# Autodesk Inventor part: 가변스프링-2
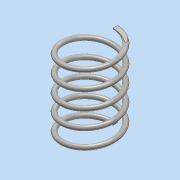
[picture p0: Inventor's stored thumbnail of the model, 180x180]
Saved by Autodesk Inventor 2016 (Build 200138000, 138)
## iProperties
Created: 2015-11
Part Number: 가변스프링-2
Material: 스테인레스 스틸
Document SubType Name: Modeling
Designer: Administrator
Density: 8 g/cm^3
Appearance: 반연마
Mass: 8.59389 g
Surface Area: 21.7235 cm^2
Volume: 1.07424 cm^3
Author: Administrator
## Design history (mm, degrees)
sketch "스케치2"
  geometry: L1 (0, 0)-(11, 0); L2 (11, 0)-(11, 36.561); L3 (11, 36.561)-(0, 36.561); L4 (0, 36.561)-(0, 0); C1 r 1 at (11, 0)
  constraints: 8 end point, 2 parallel, 1 centre point, 1 coincident, 1 horizontal, 1 perpendicular
  dimensions: "d0" = 2 diameter of C1; "d1" = 22 diameter of L2 L4; "d2" = 36.5612 distance between parallel lines of L3 L1 (derived)
feature "코일1" sketch "스케치2" pitch "d3" = 10; turns "d5" = 5; dims "d4" = 36.5612 (= d2), "d6" = 0, angle "d7" = 90 deg, angle "d8" = 90 deg, "d9" = 0, "d10" = 0
sketch "스케치3"
  geometry: L1 (0, 12)-(0, 10) reference; 1 further point
  constraints: 1 vertical alignment
extrude "돌출1" cut sketch "스케치3" distance "d11" = 10; taper "d12" = 0 deg
node "작업 평면1"
sketch "스케치4"
  geometry: L1 (0, -1)-(0, 1) reference; 1 further point
  constraints: 1 vertical alignment
extrude "돌출2" cut sketch "스케치4" distance "d13" = 10; taper "d14" = 0 deg
node "솔리드1"
node "절단 모서리 투영1"
node "절단 모서리 투영2"
